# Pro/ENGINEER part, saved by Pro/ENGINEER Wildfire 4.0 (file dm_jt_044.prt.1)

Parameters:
  METRIC = "NO"

Other parameters: PITCH, DRILL_POINT_ANGLE, DRILL_DEPTH, DRILL_DIAMETER, THREAD_DIAMETER, THREADS_PER_INCH, THREAD_DEPTH, THREAD_LENGTH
